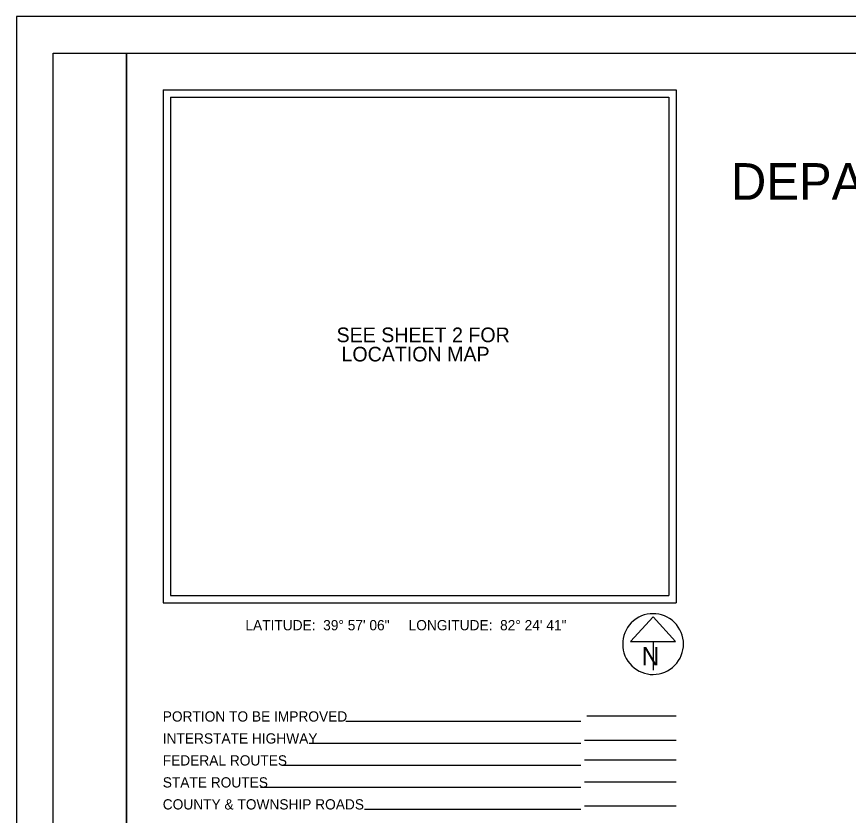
# Model space of a CAD drawing. Extents: x 0 to 34, y 0 to 22.
# Drawn here: x 0 to 11.35, y 11.1 to 22 of the extents above; entities that cross this region are included whole.
import ezdxf

# ---------------------------------------------------------------- set-up
doc = ezdxf.new("R2010")
doc.units = 0
for name, color, linetype in [('SH_Border', 7, 'Continuous'), ('SH_Cut_Line', 7, 'Continuous'), ('SH_Data', 7, 'Continuous'), ('SH_Text', 7, 'Continuous')]:
    doc.layers.add(name, color=color, linetype=linetype)

msp = doc.modelspace()

# ---------------------------------------------------------------- linework, layer by layer
at = {"layer": 'SH_Border'}
for points in [[(0.5, 21.5), (1.5, 21.5), (1.5, 0.5), (0.5, 0.5)], [(1.5, 21.5), (33.5, 21.5), (33.5, 0.5), (1.5, 0.5)]]:
    msp.add_lwpolyline(points, close=True, dxfattribs=at)
at = {"layer": 'SH_Cut_Line'}
msp.add_lwpolyline([(0, 0), (34, 0), (34, 22), (0, 22)], close=True, dxfattribs=at)
at = {"layer": 'SH_Data'}
for p, q in [((2, 21), (9, 21)), ((2, 21), (2, 14)), ((9, 21), (9, 14)), ((2.1, 20.9), (2.1, 14.1)), ((2.1, 20.9), (8.9, 20.9)), ((8.9, 20.9), (8.9, 14.1)), ((2.1, 14.1), (8.9, 14.1)), ((2.1, 14.1), (2.1, 14.1)), ((2, 14), (9, 14)), ((8.685, 13.809), (8.377, 13.468)), ((8.992, 13.468), (8.685, 13.809)), ((8.377, 13.468), (8.992, 13.468)), ((8.685, 13.468), (8.685, 13.081)), ((8.685, 13.435), (8.685, 13.435)), ((8.685, 13.435), (8.685, 13.435)), ((7.7, 12.377), (4.494, 12.377)), ((7.783, 12.455), (9, 12.455)), ((7.7, 12.077), (3.99, 12.077)), ((9, 12.121), (7.75, 12.121)), ((9, 11.849), (7.75, 11.849)), ((7.7, 11.777), (3.619, 11.777)), ((7.7, 11.477), (3.329, 11.477)), ((9, 11.549), (7.75, 11.549)), ((7.7, 11.177), (4.745, 11.177)), ((9, 11.222), (7.75, 11.222))]:
    msp.add_line(p, q, dxfattribs=at)
msp.add_arc((8.685, 13.435), 0.415, 129.7798, 129.7633, dxfattribs=at)

# ---------------------------------------------------------------- texts
for s, height, p in [('SEE SHEET 2 FOR', 0.2, (4.366, 17.556)), ('LOCATION MAP', 0.2, (4.433, 17.293)), ('N', 0.25, (8.529, 13.144))]:
    msp.add_text(s, height=height, dxfattribs=at).set_placement(p)
at = {"layer": 'SH_Text'}
for s, height, p in [('DEPARTMENT OF TRANSPORTATION', 0.5, (9.747, 19.5)), ('LATITUDE:  39° 57\' 06"     LONGITUDE:  82° 24\' 41"', 0.14, (3.122, 13.623)), ('PORTION TO BE IMPROVED', 0.14, (1.994, 12.377)), ('INTERSTATE HIGHWAY', 0.14, (1.994, 12.077)), ('FEDERAL ROUTES', 0.14, (1.994, 11.777)), ('STATE ROUTES', 0.14, (1.994, 11.477)), ('COUNTY & TOWNSHIP ROADS', 0.14, (1.994, 11.177))]:
    msp.add_text(s, height=height, dxfattribs=at).set_placement(p)

doc.saveas('drawing.dxf')
